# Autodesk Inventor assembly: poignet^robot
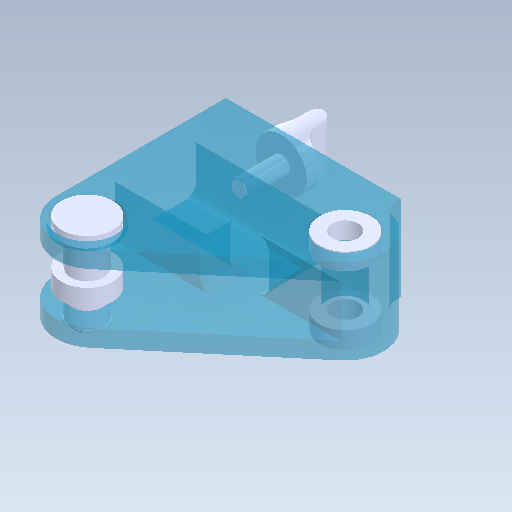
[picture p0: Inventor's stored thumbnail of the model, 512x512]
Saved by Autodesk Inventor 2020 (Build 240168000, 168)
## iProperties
Created: 2018-10
Part Number: poignet^robot
Document SubType Name: Assembly
Designer: bruno
Mass: 22.6496 g
Surface Area: 126.632 cm^2
Volume: 23.6367 cm^3
Density: 0.958239 g/cm^3
Sending System: SolidWorks 2016
Last Author: Prof
Last Saved: 2018-10-03
Author: bruno
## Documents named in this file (7)
- C:\Users\bruno\Documents\Systèmes\Mallette Bras robotisé (273265)\Dossier ressources\Maquette Dobot SW2016\poignet^robot.iam
- C:\Users\bruno\Documents\Systèmes\Mallette Bras robotisé (273265)\Dossier ressources\Maquette Dobot SW2016\_____230_A.ipt
- C:\Users\bruno\Documents\Systèmes\Mallette Bras robotisé (273265)\Dossier ressources\Maquette Dobot SW2016\MEER0005_A.ipt
- C:\Users\bruno\Documents\Systèmes\Mallette Bras robotisé (273265)\Dossier ressources\Maquette Dobot SW2016\____6__12_A.ipt
- C:\Users\bruno\Documents\Systèmes\Mallette Bras robotisé (273265)\Dossier ressources\Maquette Dobot SW2016\__________A.ipt
- C:\Users\bruno\Documents\Systèmes\Mallette Bras robotisé (273265)\Dossier ressources\Maquette Dobot SW2016\______8_A.ipt
- C:\Users\bruno\Documents\Systèmes\Mallette Bras robotisé (273265)\Dossier ressources\Maquette Dobot SW2016\_____210_A.ipt
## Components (8 placed, 6 different names)
1. _____230_A:1
2. MEER0005_A:1
3. ____6__12_A:1
4. __________A:1
5. ______8_A:1
6. ____6__12_A:2
7. ____6__12_A:3
8. _____210_A:1
